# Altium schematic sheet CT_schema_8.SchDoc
size 274 x 160 mm
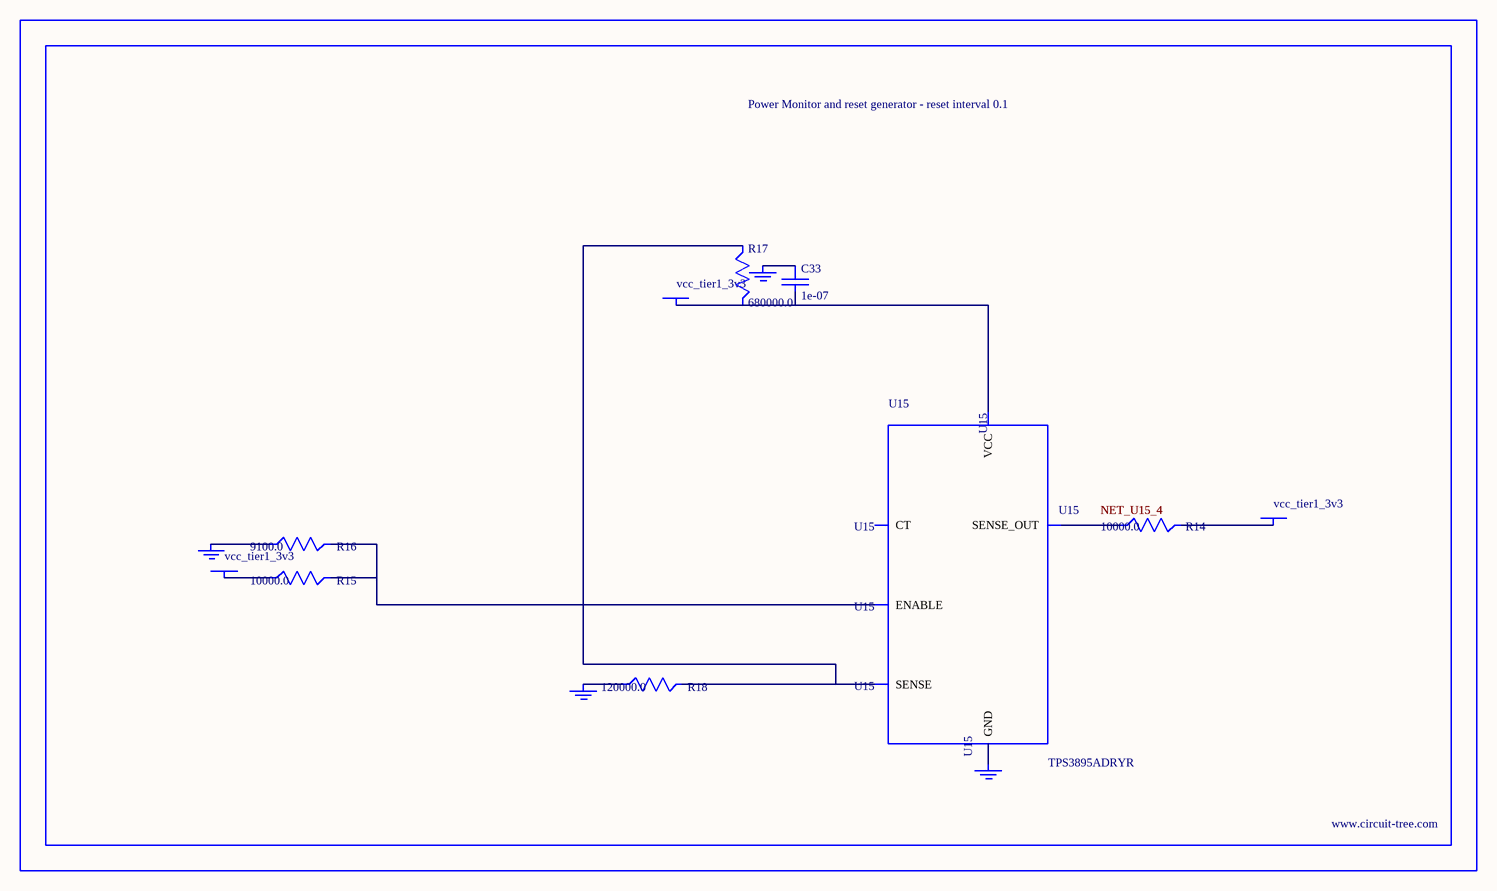
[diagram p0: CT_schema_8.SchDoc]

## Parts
BORDER7  (no value)
C33  1e-07  [C0402]
GND_INSTANCE_7_0  (no value)
GND_INSTANCE_7_1  (no value)
GND_INSTANCE_7_2  (no value)
GND_INSTANCE_7_3  (no value)
POWER_INSTANCE_7_0  vcc_tier1_3v3
POWER_INSTANCE_7_1  vcc_tier1_3v3
POWER_INSTANCE_7_2  vcc_tier1_3v3
R14  10000.0  [R0603]
R15  10000.0  [R0603]
R16  9100.0  [R0603]
R17  680000.0  [R0603]
R18  120000.0  [R0603]
U15  TPS3895ADRYR  [SON-6]

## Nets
NetC33_1: C33.1 GND_INSTANCE_7_2.0(GND)
NetC33_2: C33.2 POWER_INSTANCE_7_2.0(PWR) R17.2 U15.6(VCC)
NetGND_INSTANCE_7_0_0: GND_INSTANCE_7_0.0(GND) R16.1
NetGND_INSTANCE_7_1_0: GND_INSTANCE_7_1.0(GND) R18.1
NetGND_INSTANCE_7_3_0: GND_INSTANCE_7_3.0(GND) U15.2(GND)
NetPOWER_INSTANCE_7_0_0: POWER_INSTANCE_7_0.0(PWR) R15.1
NetPOWER_INSTANCE_7_1_0: POWER_INSTANCE_7_1.0(PWR) R14.2
NetR14_1: R14.1 U15.4(SENSE_OUT)
NetR15_2: R15.2 R16.2 U15.1(ENABLE)
NetR17_1: R17.1 R18.2 U15.3(SENSE)

Not connected (* = marked no-connect by the designer): U15 5(CT)

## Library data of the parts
BORDER7 = BORDER_PAGE7
C33 = C0402C104K3RACTU
GND_INSTANCE_7_0-GND_INSTANCE_7_3 = GND
POWER_INSTANCE_7_0-POWER_INSTANCE_7_2 = PWR
R14 R15 = RC0603JR-0710KL
R16 = RC0603JR-079K1L
R17 = RC0603JR-07680KL
R18 = RC0603JR-07120KL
